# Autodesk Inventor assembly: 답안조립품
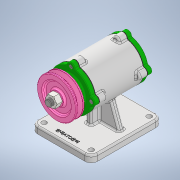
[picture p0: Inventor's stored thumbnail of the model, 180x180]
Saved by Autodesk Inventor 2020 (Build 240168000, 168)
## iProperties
Created: 2022-11
Part Number: 답안조립품
Document SubType Name: Assembly
Designer: owner
Author: owner
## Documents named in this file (12)
- C:\Users\owner\Desktop\721108V1017\답안조립품.iam
- C:\Users\owner\Desktop\721108V1017\본체.ipt
- C:\Users\owner\Desktop\721108V1017\V-벨트풀리.ipt
- C:\Users\owner\Desktop\721108V1017\개스킷.ipt
- C:\Users\owner\Desktop\721108V1017\너트 M12 x 1.25.ipt
- C:\Users\owner\Desktop\721108V1017\뒤커버.ipt
- C:\Users\owner\Desktop\721108V1017\베어링 6204.ipt
- C:\Users\owner\Desktop\721108V1017\볼트 M4 x 12.ipt
- C:\Users\owner\Desktop\721108V1017\앞커버.ipt
- C:\Users\owner\Desktop\721108V1017\오일 실.ipt
- C:\Users\owner\Desktop\721108V1017\축.ipt
- C:\Users\owner\Desktop\721108V1017\키 4 x 4.ipt
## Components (8 placed, 6 different names)
1. V-벨트풀리:1
2. 개스킷:1
3. KS B 1012 클래스 1 일반 - 미터 M12x1.25:1
4. KS B 2023 6204 - 20 x 47 x 14:1
5. KS B 2804 D D - 20 32 8:1
6. KS B 1311 (I) 4 x 4 x 12:1
7. KS B 2023 6204 - 20 x 47 x 14:2
8. 개스킷:2
